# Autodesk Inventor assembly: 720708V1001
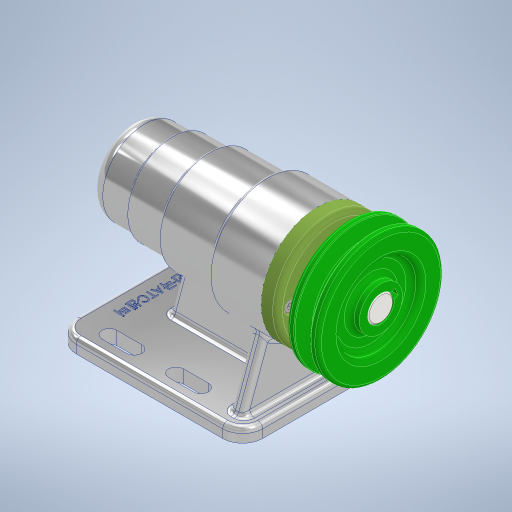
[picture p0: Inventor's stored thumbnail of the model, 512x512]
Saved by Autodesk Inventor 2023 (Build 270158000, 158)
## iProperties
Created: 2022-07
Part Number: 720708V1001
Document SubType Name: Assembly
Designer: owner
Author: owner
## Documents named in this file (12)
- C:\Users\owner\Desktop\720708V1001\720708V1001.iam
- C:\Users\owner\Desktop\720708V1001\본체.ipt
- C:\Users\owner\Desktop\720708V1001\V벨트풀리.ipt
- C:\Users\owner\Desktop\720708V1001\멈춤나사 M3.ipt
- C:\Users\owner\Desktop\720708V1001\베어링 6004.ipt
- C:\Users\owner\Desktop\720708V1001\베어링 51202.ipt
- C:\Users\owner\Desktop\720708V1001\볼트 M4.ipt
- C:\Users\owner\Desktop\720708V1001\어댑터슬리브.ipt
- C:\Users\owner\Desktop\720708V1001\오일 실 20x35x7.ipt
- C:\Users\owner\Desktop\720708V1001\축.ipt
- C:\Users\owner\Desktop\720708V1001\커버.ipt
- C:\Users\owner\Desktop\720708V1001\키 5x5.ipt
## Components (1 placed, 1 different names)
1. V벨트풀리:1
